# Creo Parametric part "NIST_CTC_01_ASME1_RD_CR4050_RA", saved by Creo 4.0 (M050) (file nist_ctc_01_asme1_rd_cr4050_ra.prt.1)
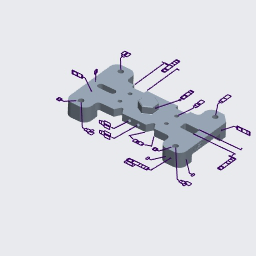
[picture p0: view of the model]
Units: millimeter Kilogram Sec (mmKs); MM, KILOGRAM, SECS

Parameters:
  PART_NUMBER = "NIST PMI CTC 01 ASME1"
  REVISION = "D"
  DESCRIPTION = "NIST PMI test model downloaded from http://go.usa.gov/mGVm"

Created from: NIST_CTC_01_ASME1_CR4050_RD.PRT

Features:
  1. datum plane "RIGHT"
  2. datum plane "TOP"
  3. datum plane "FRONT"
  4. coordinate system
  5. curve
  6. protrusion
  7. curve
  8. protrusion
  9. curve
  10. pattern
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
Other named items: DATUM_TAG_A, GP10, DATUM_TAG_B, AD534, AD537, GP12, DRF1, GP13, DRF2, DATUM_TAG_C, AD538, AD541, GP14, AD544, GP15, GP16, AD549, AD552, AD553, AD554, AD556, MBD_0, ANNOT_LAYER_STATE0006

Layers: ALL_ANNOTATIONS, ALL_AXES, ALL_CSYS, ALL_CURVES, ALL_PLANES, ALL_POINTS, ALL_QUILTS, DEF_CSYS, DEF_PLANES

Notes: �⏥ | 0.2 | �⌖ | 0.75 | A | B | C

Surfaces: 78 plane, 59 cylinder, 4 cone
